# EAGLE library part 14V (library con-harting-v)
CONNECTOR
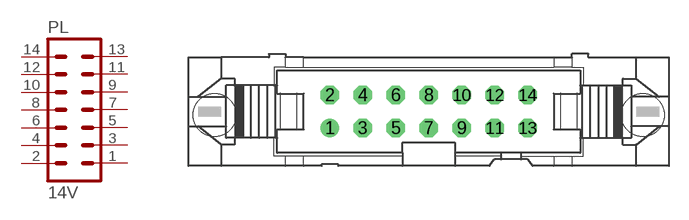
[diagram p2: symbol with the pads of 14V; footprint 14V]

Designator prefix PL

## 14V (OC_FARNELL: unknown; OC_NEWARK: unknown)  [14V]
1  1  pas
2  2  pas
3  3  pas
4  4  pas
5  5  pas
6  6  pas
7  7  pas
8  8  pas
9  9  pas
10  10  pas
11  11  pas
12  12  pas
13  13  pas
14  14  pas

## Footprint 14V (pad centres in mm)
CONNECTOR
drill 0.914 round: 1 -7.62,-1.27
drill 0.914 octagon: 2 -7.62,1.27; 3 -5.08,-1.27; 4 -5.08,1.27; 5 -2.54,-1.27; 6 -2.54,1.27; 7 0,-1.27; 8 0,1.27; 9 2.54,-1.27; 10 2.54,1.27; 11 5.08,-1.27; 12 5.08,1.27; 13 7.62,-1.27; 14 7.62,1.27
hole 3.302 at 16.51,-0.254
hole 3.302 at -16.51,-0.254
